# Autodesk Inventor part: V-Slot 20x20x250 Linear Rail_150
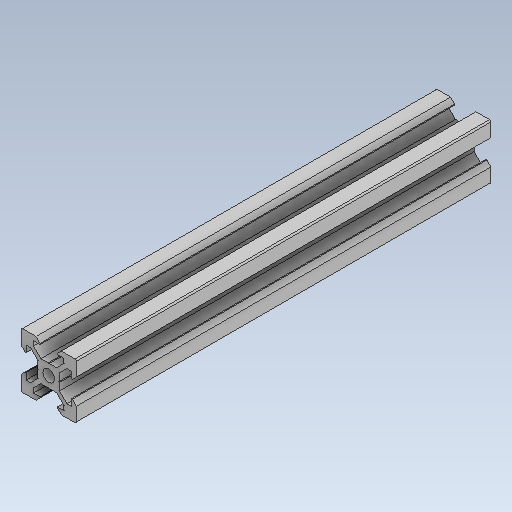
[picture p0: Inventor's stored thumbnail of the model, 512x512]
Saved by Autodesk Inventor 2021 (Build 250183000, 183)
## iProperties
Created: 2026-10
Part Number: V-Slot 20x20x250 Linear Rail_150
Material: Generic
Document SubType Name: Modeling
Designer: hp
Density: 1 g/cm^3
Appearance: Default
Author: hp
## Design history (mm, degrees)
feature "Body1"
body "Solid1"
